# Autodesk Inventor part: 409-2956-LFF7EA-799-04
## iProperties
Created: 2010-11
Part Number: 409-2956-LFF7EA-799-04
Material: 3/4" OD TUBE - SS
Document SubType Name: Modeling
Designer: S. Boerckel
Engineer: Steve Boerckel
Mass: 731.966 g
Surface Area: 1099.2 cm^2
Volume: 90.5898 cm^3
Density: 8.08 g/cm^3
Description: DRAIN TUBING
Length: 39.254 in
Author: S. Boerckel
Revision Number: 0
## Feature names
1. Sweep2
